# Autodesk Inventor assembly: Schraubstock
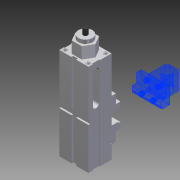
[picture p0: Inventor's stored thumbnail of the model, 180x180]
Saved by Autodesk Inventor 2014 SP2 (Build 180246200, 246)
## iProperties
Created: 2015-06
Part Number: Schraubstock
Document SubType Name: Assembly
Designer: e_krauts
Mass: 4334.15 g
Surface Area: 5057.15 cm^2
Volume: 4334.15 cm^3
Density: 1 g/cm^3
Sending System: SolidWorks 2011
Last Author: e_boekem
Author: e_krauts
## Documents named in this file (5)
- C:\Users\e_krauts\AppData\Local\SolidCAM Temporary Files\NADELHALTER_UNTEN\Schraubstock.iam
- C:\Users\e_krauts\AppData\Local\SolidCAM Temporary Files\NADELHALTER_UNTEN\Backe20x40.ipt
- C:\Users\e_krauts\AppData\Local\SolidCAM Temporary Files\NADELHALTER_UNTEN\Unterteil.ipt
- C:\Users\e_krauts\AppData\Local\SolidCAM Temporary Files\NADELHALTER_UNTEN\Backe 40 x 20 ohne.ipt
- C:\Users\e_krauts\AppData\Local\SolidCAM Temporary Files\NADELHALTER_UNTEN\Spindel.ipt
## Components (4 placed, 4 different names)
1. Backe20x40:1 — Passend:2, Fluchtend:1
2. Unterteil:1 — Passend:1, Passend:2, Passend:4, Passend:5, Fluchtend:1
3. Backe 40 x 20 ohne:1 — Passend:3, Passend:4
4. Spindel:2 — Passend:1, Passend:3, Passend:5
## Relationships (6: Mate 5, Flush 1)
- Passend:1 [Mate]: Unterteil:1 ↔ Spindel:2
- Passend:2 [Mate]: Backe20x40:1 ↔ Unterteil:1
- Passend:3 [Mate]: Backe 40 x 20 ohne:1 ↔ Spindel:2
- Passend:4 [Mate]: Unterteil:1 ↔ Backe 40 x 20 ohne:1
- Passend:5 [Mate]: Unterteil:1 ↔ Spindel:2
- Fluchtend:1 [Flush]: Backe20x40:1 ↔ Unterteil:1
